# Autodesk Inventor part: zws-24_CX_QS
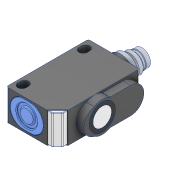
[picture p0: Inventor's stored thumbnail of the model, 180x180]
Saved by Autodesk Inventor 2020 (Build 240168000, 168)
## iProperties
Created: 2025-04
Part Number: zws-24_CX_QS
Material: Generisch
Description: STEP AP214
Document SubType Name: Modeling
Designer: Oliver Liedtke
Density: 1 g/cm^3
Appearance: Vorgabe
Title: zws-24_CX_QS.STEP
Revision Number: ANY
Sending System: SolidWorks 2024
Preprocessor: SwSTEP 2.0
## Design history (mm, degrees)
feature "Verrundung1"
node "Volumenkörper1"
